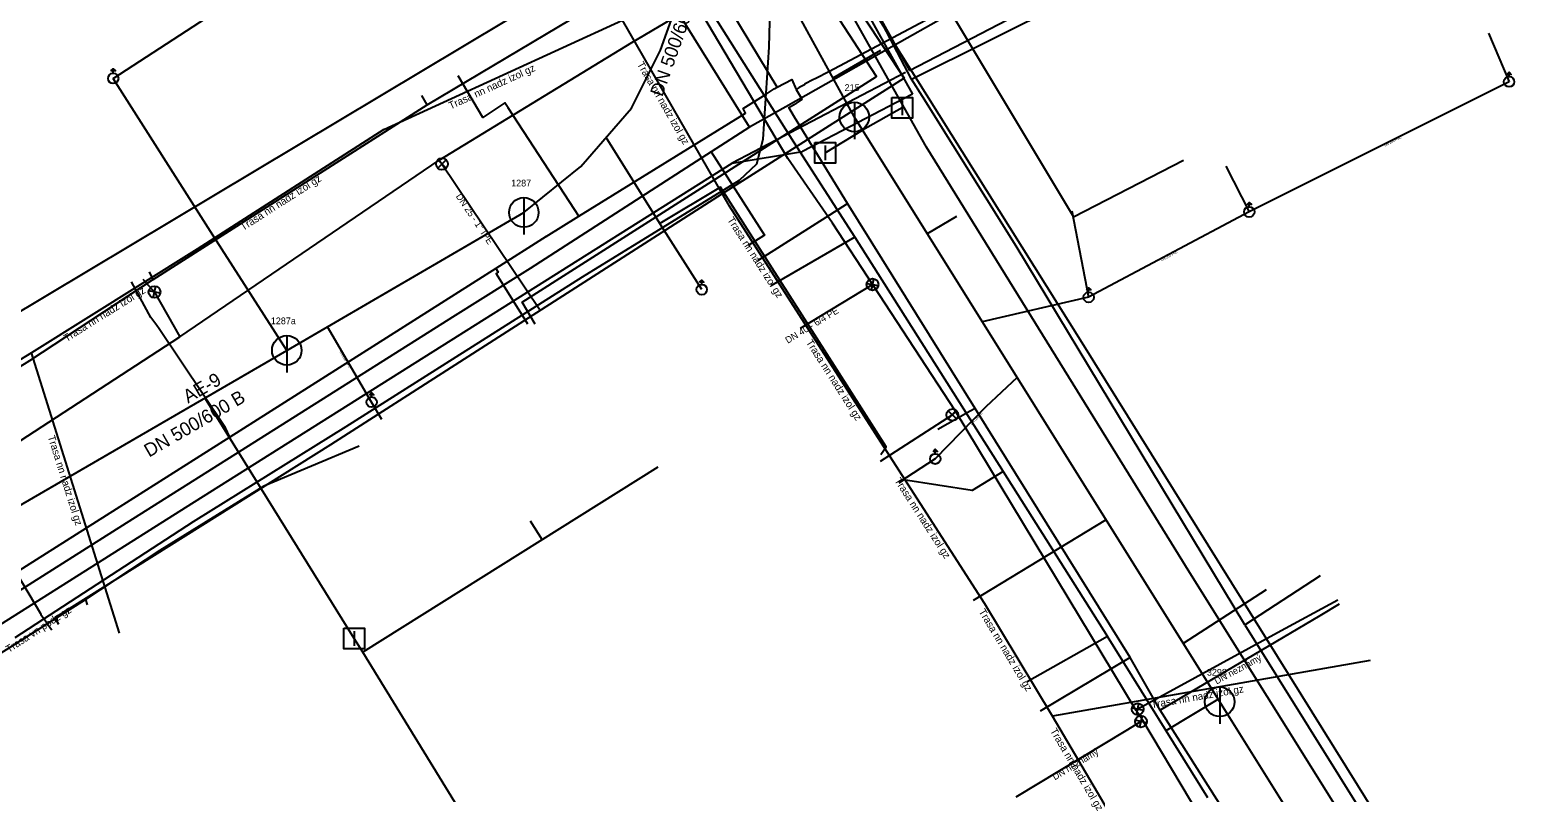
# Model space of a CAD drawing. Extents: x -493753 to -49291, y -1127285 to -112662.
# Drawn here: x -492897.5 to -492795.3, y -1126842.6 to -1126791 of the extents above; entities that cross this region are included whole.
import ezdxf

# ---------------------------------------------------------------- set-up
doc = ezdxf.new("R2010")
doc.units = 0
for name, color, linetype in [('Vrstva 1', 7, 'Continuous'), ('Vrstva 11', 7, 'Continuous'), ('Vrstva 15', 7, 'Continuous'), ('Vrstva 17', 7, 'Continuous'), ('Vrstva 19', 7, 'Continuous'), ('Vrstva 20', 7, 'Continuous'), ('Vrstva 22', 7, 'Continuous'), ('Vrstva 24', 7, 'Continuous'), ('Vrstva 26', 7, 'Continuous'), ('Vrstva 37', 7, 'Continuous'), ('Vrstva 39', 7, 'Continuous'), ('Vrstva 5', 7, 'Continuous'), ('Vrstva 6', 7, 'Continuous'), ('Vrstva 9', 7, 'Continuous')]:
    doc.layers.add(name, color=color, linetype=linetype)

# ---------------------------------------------------------------- blocks, each defined once
blk = doc.blocks.new('_UZAV0')
at = {"layer": 'Vrstva 1'}
for p, q in [((-0.035, -0.035), (0.035, 0.035)), ((0.035, -0.035), (-0.035, 0.035))]:
    blk.add_line(p, q, dxfattribs=at)
for radius in [0.05, 0.0025]:
    blk.add_circle((0, 0), radius, dxfattribs=at)
blk = doc.blocks.new('_VPUST')
at = {"layer": 'Vrstva 1'}
blk.add_line((0, 0.025), (0, -0.025), dxfattribs=at)
blk.add_lwpolyline([(-0.035, 0.035), (0.035, 0.035), (0.035, -0.035), (-0.035, -0.035), (-0.035, 0.035)], dxfattribs=at)
blk = doc.blocks.new('_SACHT')
at = {"layer": 'Vrstva 1'}
blk.add_line((0, 0.035), (0, 0.05), dxfattribs=at)
blk.add_lwpolyline([(-0.015, 0.05), (0, 0.065), (0.015, 0.05), (0.0025, 0.05)], close=True, dxfattribs=at)
blk.add_circle((0, 0), 0.035, dxfattribs=at)
blk = doc.blocks.new('_SACH0')
at = {"layer": 'Vrstva 1'}
blk.add_line((0, 0.05), (0, -0.075), dxfattribs=at)
blk.add_circle((0, 0), 0.05, dxfattribs=at)

msp = doc.modelspace()

# ---------------------------------------------------------------- linework, layer by layer
at = {"layer": 'Vrstva 1'}
for p, q in [((-492846.86, -1126794.83), (-492851.27, -1126787.5)), ((-492843.3, -1126803.48), (-492842.1, -1126802.71)), ((-492833.45, -1126816.59), (-492833.79, -1126816.78)), ((-492833.79, -1126816.78), (-492835.97, -1126818)), ((-492808.78, -1126829.85), (-492810.11, -1126830.63)), ((-492810.11, -1126830.63), (-492820.92, -1126837.03)), ((-492896.08, -1126831.47), (-492896, -1126831.58)), ((-492822.95, -1126833.45), (-492829.05, -1126837.09))]:
    msp.add_line(p, q, dxfattribs=at)
for points in [[(-492836.47, -1126790.12), (-492839.74, -1126791.86), (-492843.37, -1126793.78), (-492844.25, -1126794.24), (-492844.25, -1126794.24), (-492844.44, -1126794.34), (-492844.96, -1126794.61), (-492845.01, -1126794.66), (-492845.36, -1126794.86), (-492845.58, -1126794.99)], [(-492860.3, -1126803.57), (-492860.6, -1126803.11), (-492865.08, -1126796.23), (-492865.31, -1126795.89), (-492866.8, -1126796.88), (-492868.46, -1126794.05)], [(-492862.5, -1126804.93), (-492860.3, -1126803.57), (-492849.36, -1126796.81), (-492849.01, -1126796.59), (-492849.17, -1126796.27), (-492847.6, -1126795.29), (-492847.06, -1126794.95), (-492846.86, -1126794.83), (-492845.87, -1126794.31), (-492845.58, -1126794.99), (-492845.24, -1126795.55), (-492845.18, -1126795.67), (-492845.59, -1126795.94)], [(-492845.69, -1126796.86), (-492846.08, -1126796.21), (-492845.59, -1126795.94)], [(-492785.47, -1126893.44), (-492789.17, -1126887.53), (-492793.46, -1126880.64), (-492799.87, -1126870.52), (-492802.28, -1126866.71), (-492807.06, -1126859.45), (-492812.73, -1126850.83), (-492816.5, -1126843.99), (-492820.92, -1126837.03), (-492822.95, -1126833.45), (-492833.45, -1126816.59), (-492842.1, -1126802.71), (-492845.69, -1126796.86)], [(-492848.18, -1126806.57), (-492847.74, -1126806.29), (-492843.3, -1126803.48)], [(-492862.5, -1126804.93), (-492865.92, -1126807.1), (-492883.94, -1126818.54), (-492898.42, -1126827.7), (-492903.21, -1126830.75), (-492903.38, -1126830.86), (-492903.38, -1126830.86), (-492905.79, -1126832.39), (-492910.03, -1126835.06), (-492919.37, -1126840.86)], [(-492865.92, -1126807.1), (-492865.76, -1126807.36), (-492865.89, -1126807.44), (-492865.84, -1126807.52)], [(-492863.74, -1126810.87), (-492864.11, -1126810.28), (-492864.65, -1126809.43), (-492865.84, -1126807.52)], [(-492883.94, -1126818.54), (-492884.24, -1126817.89), (-492888.73, -1126811.2), (-492888.89, -1126810.97), (-492889.28, -1126810.42), (-492890.61, -1126808.01)], [(-492898.42, -1126827.7), (-492896.77, -1126830.47), (-492896.73, -1126830.54), (-492896.42, -1126830.98), (-492896.34, -1126831.1), (-492896.08, -1126831.47)]]:
    msp.add_lwpolyline(points, dxfattribs=at)
at = {"layer": 'Vrstva 11'}
for points in [[(-492848.73, -1126797.53), (-492854.56, -1126788.15), (-492854.38, -1126786.02), (-492853.2, -1126784.39), (-492859.9, -1126772.1), (-492871.87, -1126750.4), (-492886.74, -1126723.34), (-492898.4, -1126701.86), (-492908, -1126684.26), (-492916.54, -1126668.65), (-492921.45, -1126660.08), (-492926.55, -1126650.44), (-492932.03, -1126640.6), (-492935.8, -1126632.89)], [(-492799.37, -1126772.01), (-492815.12, -1126779.81), (-492834.32, -1126789.41), (-492840.18, -1126792.71), (-492846.28, -1126796.15), (-492848.73, -1126797.53)], [(-492841.39, -1126779.25), (-492846.47, -1126781.81), (-492838.25, -1126794.22), (-492850.91, -1126802.26), (-492877.11, -1126819.04), (-492895.8, -1126830.76), (-492895.54, -1126831.19)], [(-492841.39, -1126779.25), (-492828.07, -1126801.46)], [(-492848.73, -1126797.53), (-492851.33, -1126799.21)], [(-492851.33, -1126799.21), (-492863.6, -1126807.1), (-492868.67, -1126810.3), (-492890.52, -1126824.08), (-492904.79, -1126833.09), (-492915.31, -1126839.73), (-492925.93, -1126846.41)], [(-492851.33, -1126799.21), (-492847.71, -1126804.84), (-492848.82, -1126805.56)], [(-492828.07, -1126801.46), (-492826.79, -1126803.6), (-492819.34, -1126799.76)]]:
    msp.add_lwpolyline(points, dxfattribs=at)
at = {"layer": 'Vrstva 15'}
for p, q in [((-492891.84, -1126794.23), (-492875.54, -1126783.64)), ((-492841.63, -1126796.85), (-492848.75, -1126783.83)), ((-492798.67, -1126791.17), (-492797.28, -1126794.46)), ((-492839.87, -1126792.35), (-492843.08, -1126794.21)), ((-492797.28, -1126794.46), (-492814.88, -1126803.28)), ((-492838.39, -1126796.23), (-492841.08, -1126797.74)), ((-492816.88, -1126836.45), (-492841.63, -1126796.85)), ((-492854.81, -1126804.05), (-492858.44, -1126798.23)), ((-492843.61, -1126799.27), (-492841.08, -1126797.74)), ((-492816.47, -1126800.17), (-492814.88, -1126803.28)), ((-492880.08, -1126812.65), (-492864.02, -1126803.31)), ((-492826.9, -1126803.21), (-492825.76, -1126809.06)), ((-492814.88, -1126803.28), (-492825.76, -1126809.06)), ((-492834.72, -1126803.58), (-492836.69, -1126804.76)), ((-492825.76, -1126809.06), (-492832.97, -1126810.71)), ((-492874.33, -1126816.16), (-492877.33, -1126811.05)), ((-492906.42, -1126827.95), (-492880.08, -1126812.65)), ((-492875.51, -1126832.17), (-492885.63, -1126815.87)), ((-492873.65, -1126817.33), (-492874.33, -1126816.16)), ((-492854.94, -1126820.56), (-492874.93, -1126833.1)), ((-492836.15, -1126820), (-492838.63, -1126821.59)), ((-492863.59, -1126824.19), (-492862.78, -1126825.48)), ((-492833.55, -1126829.56), (-492824.59, -1126824.12)), ((-492813.74, -1126828.87), (-492819.35, -1126832.51)), ((-492874.93, -1126833.1), (-492875.51, -1126832.17)), ((-492866.83, -1126846.29), (-492874.93, -1126833.1)), ((-492820.5, -1126838.4), (-492816.99, -1126836.28)), ((-492782.29, -1126891.79), (-492816.88, -1126836.45))]:
    msp.add_line(p, q, dxfattribs=at)
for points in [[(-492864.02, -1126803.31), (-492860.16, -1126800.21), (-492856.72, -1126796.26), (-492854.76, -1126792.33), (-492853.47, -1126788.71), (-492852.82, -1126784.59), (-492852.84, -1126780.6), (-492853.67, -1126775.98), (-492855.18, -1126772.05)], [(-492880.08, -1126812.65), (-492885.25, -1126804.6), (-492891.84, -1126794.23)], [(-492839.83, -1126819.71), (-492839.48, -1126819.19), (-492850.69, -1126801.61), (-492854.81, -1126804.05)], [(-492851.97, -1126808.54), (-492854.69, -1126804.24), (-492854.81, -1126804.05)], [(-492830.61, -1126814.48), (-492832.73, -1126816.48), (-492836.15, -1126820)]]:
    msp.add_lwpolyline(points, dxfattribs=at)
at = {"layer": 'Vrstva 20'}
for p, q in [((-492845.27, -1126811.15), (-492840.4, -1126808.19)), ((-492808.87, -1126829.56), (-492812.97, -1126831.79)), ((-492830.67, -1126842.89), (-492823.22, -1126838.39))]:
    msp.add_line(p, q, dxfattribs=at)
for points in [[(-492970.22, -1126863.36), (-492958.22, -1126855.33), (-492945.51, -1126848.03), (-492940.77, -1126845.12), (-492925.74, -1126835.49), (-492904.65, -1126823), (-492904.05, -1126822.61), (-492887.33, -1126811.73), (-492869.75, -1126799.77), (-492856.71, -1126791.8), (-492853.07, -1126789.65)], [(-492786.68, -1126894.07), (-492787.42, -1126892.88), (-492788.56, -1126891.12), (-492791.28, -1126887.34), (-492800.45, -1126872.14), (-492806.36, -1126863.49), (-492810.7, -1126856.3), (-492813.24, -1126852.47), (-492818.85, -1126843.14), (-492822.1, -1126837.71), (-492822.55, -1126837.04), (-492834.77, -1126816.78), (-492843.12, -1126804.04), (-492846.14, -1126799.66), (-492852.32, -1126789.23)], [(-492869.75, -1126799.77), (-492869.57, -1126800.03), (-492862.95, -1126809.86)], [(-492889.83, -1126807.82), (-492889.04, -1126808.7), (-492887.33, -1126811.73)], [(-492834.77, -1126816.78), (-492834.99, -1126817.02), (-492839.88, -1126820.17)], [(-492812.97, -1126831.79), (-492822.44, -1126836.95), (-492822.55, -1126837.04)], [(-492823.22, -1126838.39), (-492822.22, -1126837.79), (-492822.1, -1126837.71)]]:
    msp.add_lwpolyline(points, dxfattribs=at)
at = {"layer": 'Vrstva 26'}
for p, q in [((-492861.22, -1126753.01), (-492837.7, -1126795.29)), ((-492860.7, -1126752.71), (-492837.9, -1126793.7)), ((-492837.9, -1126793.7), (-492813.31, -1126780.85)), ((-492836.75, -1126798.9), (-492842.69, -1126788.32)), ((-492838.16, -1126793.84), (-492849.91, -1126799.98)), ((-492837.7, -1126795.29), (-492845.15, -1126799.19)), ((-492849.91, -1126799.98), (-492845.15, -1126799.19)), ((-492824.87, -1126818.07), (-492836.75, -1126798.9)), ((-492886.94, -1126823.29), (-492849.91, -1126799.98)), ((-492818.91, -1126827.72), (-492824.87, -1126818.07)), ((-492921.27, -1126844.96), (-492886.94, -1126823.29)), ((-492808.42, -1126844.48), (-492818.91, -1126827.72))]:
    msp.add_line(p, q, dxfattribs=at)
at = {"layer": 'Vrstva 37'}
msp.add_line((-492859.57, -1126786.93), (-492899.16, -1126810.62), dxfattribs=at)
at = {"layer": 'Vrstva 39'}
for points in [[(-492837.75, -1126794.28), (-492844.99, -1126780.49)], [(-492870.58, -1126796.02), (-492853.69, -1126785.96)], [(-492853.69, -1126785.96), (-492845.76, -1126798.53), (-492841.59, -1126804.98)], [(-492837.75, -1126794.28), (-492821.94, -1126786.39)], [(-492837.02, -1126795.45), (-492837.75, -1126794.28)], [(-492889.14, -1126807.86), (-492870.58, -1126796.02)], [(-492870.58, -1126796.02), (-492870.94, -1126795.4)], [(-492815.19, -1126831.24), (-492830.68, -1126805.6), (-492837.02, -1126795.45)], [(-492841.59, -1126804.98), (-492847.28, -1126808.29)], [(-492841.59, -1126804.98), (-492831.56, -1126820.85)], [(-492889.14, -1126807.86), (-492889.39, -1126807.33)], [(-492889.14, -1126807.86), (-492897.51, -1126813.36), (-492916.14, -1126824.91), (-492935.64, -1126837.46), (-492943.74, -1126842.54)], [(-492875.17, -1126819.13), (-492881.63, -1126821.85), (-492888.69, -1126826.2), (-492893.71, -1126829.53)], [(-492831.56, -1126820.85), (-492833.65, -1126822.14), (-492838.3, -1126821.41), (-492838.63, -1126821.64)], [(-492831.56, -1126820.85), (-492824.48, -1126832.04)], [(-492815.19, -1126831.24), (-492810.05, -1126827.9)], [(-492913.49, -1126842), (-492910.42, -1126840.06), (-492907.08, -1126837.96), (-492893.71, -1126829.53)], [(-492893.71, -1126829.53), (-492893.61, -1126829.89)], [(-492824.48, -1126832.04), (-492829.93, -1126835.1)], [(-492817.68, -1126842.95), (-492824.48, -1126832.04)], [(-492815.19, -1126831.24), (-492804.46, -1126848.41)]]:
    msp.add_lwpolyline(points, dxfattribs=at)
at = {"layer": 'Vrstva 5'}
for points in [[(-492863.25, -1126810.88), (-492864.13, -1126809.38), (-492840.13, -1126794.11), (-492848.76, -1126780.82), (-492859.92, -1126760.67), (-492861.29, -1126757.87), (-492860.64, -1126755.54), (-492859.68, -1126754.76), (-492856.69, -1126753.45)], [(-492873.51, -1126797.69), (-492857.33, -1126790.3)], [(-492850.08, -1126802.88), (-492857.33, -1126790.3)], [(-492873.51, -1126797.69), (-492886.16, -1126805.8)], [(-492844.8, -1126811.12), (-492850.08, -1126802.88)], [(-492886.16, -1126805.8), (-492897.38, -1126812.82)], [(-492839.44, -1126819.49), (-492844.8, -1126811.12)], [(-492897.38, -1126812.82), (-492916.42, -1126824.45)], [(-492891.41, -1126831.8), (-492897.38, -1126812.82)], [(-492832.79, -1126829.81), (-492839.44, -1126819.49)], [(-492828.22, -1126837.42), (-492832.79, -1126829.81)], [(-492806.69, -1126833.65), (-492828.22, -1126837.42)], [(-492823.15, -1126846), (-492828.22, -1126837.42)]]:
    msp.add_lwpolyline(points, dxfattribs=at)
at = {"layer": 'Vrstva 6'}
for points in [[(-492898.47, -1126832.09), (-492886.41, -1126824.24), (-492876.05, -1126817.81), (-492860.04, -1126807.68), (-492849.41, -1126801.13), (-492848.23, -1126800.02), (-492847.8, -1126798.34), (-492847.4, -1126792.12), (-492847.23, -1126785.11), (-492846.68, -1126781.31), (-492846.74, -1126780.22), (-492852.23, -1126770.3), (-492858.08, -1126759.81), (-492859.14, -1126757.56), (-492858.99, -1126756.88), (-492856.69, -1126753.45)], [(-492856.69, -1126753.45), (-492858.36, -1126756.9), (-492854, -1126764.44), (-492846.25, -1126778.79), (-492844.82, -1126782.46), (-492836.75, -1126795.34), (-492826.22, -1126812.12), (-492807.54, -1126842.09), (-492794.08, -1126863.74), (-492778.12, -1126889.63)]]:
    msp.add_lwpolyline(points, dxfattribs=at)

# ---------------------------------------------------------------- block references
at = {"layer": 'Vrstva 17'}
for name, p, xscale, yscale in [('_SACHT', (-492891.84, -1126794.23), 9.998750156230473, 9.998750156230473), ('_SACHT', (-492797.28, -1126794.46), 9.998750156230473, 9.998750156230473), ('_SACH0', (-492841.63, -1126796.85), 19.997500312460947, 19.997500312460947), ('_VPUST', (-492838.39, -1126796.23), 19.997500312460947, 19.997500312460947), ('_VPUST', (-492843.61, -1126799.27), 19.997500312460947, 19.997500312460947), ('_SACH0', (-492864.02, -1126803.31), 19.997500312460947, 19.997500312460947), ('_SACHT', (-492814.88, -1126803.28), 9.998750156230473, 9.998750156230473), ('_SACHT', (-492851.97, -1126808.54), 9.998750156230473, 9.998750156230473), ('_SACHT', (-492825.76, -1126809.06), 9.998750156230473, 9.998750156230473), ('_SACH0', (-492880.08, -1126812.65), 19.997500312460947, 19.997500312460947), ('_SACHT', (-492874.33, -1126816.16), 9.998750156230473, 9.998750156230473), ('_SACHT', (-492836.15, -1126820), 9.998750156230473, 9.998750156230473), ('_VPUST', (-492875.51, -1126832.17), 19.997500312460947, 19.997500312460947), ('_SACH0', (-492816.88, -1126836.45), 19.997500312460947, 19.997500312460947)]:
    msp.add_blockref(name, p, dxfattribs=dict(at, xscale=xscale, yscale=yscale))
at = {"layer": 'Vrstva 22', "xscale": 7.999000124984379, "yscale": 7.999000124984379}
for p in [(-492869.57, -1126800.03), (-492834.99, -1126817.02)]:
    msp.add_blockref('_UZAV0', p, dxfattribs=at)
at = {"layer": 'Vrstva 22'}
for p, xscale, yscale, rotation in [((-492889.04, -1126808.7), 7.999000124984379, 7.99900012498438, 32.53708333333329), ((-492840.4, -1126808.19), 7.999000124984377, 7.999000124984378, -56.2388406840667), ((-492822.44, -1126836.95), 7.999000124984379, 7.999000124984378, -56.585208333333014), ((-492822.22, -1126837.79), 7.999000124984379, 7.999000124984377, 121.658366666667)]:
    msp.add_blockref('_UZAV0', p, dxfattribs=dict(at, xscale=xscale, yscale=yscale, rotation=rotation))

# ---------------------------------------------------------------- texts
at = {"layer": 'Vrstva 19'}
for s, height, rotation, p in [('DN 500/600 B', 0.9099, 70.4144, (-492854.64, -1126795.52)), ('DN 200 PVC', 0.16, 26.635, (-492805.69, -1126798.85)), ('DN 200 PVC', 0.16, 27.9687, (-492820.81, -1126806.62)), ('DN 200 PVC', 0.16, 300.3416, (-492876.51, -1126812.75)), ('AE-9', 0.91, 30.1603, (-492886.77, -1126816.26)), ('DN 500/600 B', 0.9099, 30.1603, (-492889.41, -1126819.92)), ('DN 250 PE', 0.16, 45.8129, (-492833.7, -1126817.71))]:
    msp.add_text(s, height=height, rotation=rotation, dxfattribs=at).set_placement(p)
for s, p in [('215', (-492842.29, -1126795.08)), ('1287', (-492864.88, -1126801.55)), ('1287a', (-492881.16, -1126810.88)), ('3298', (-492817.75, -1126834.68))]:
    msp.add_text(s, height=0.455, dxfattribs=at).set_placement(p)
at = {"layer": 'Vrstva 24'}
for s, rotation, p in [("DN 25 - 1'' IPE", 303.9582, (-492868.65, -1126802.22)), ('DN 40 - 6/4 PE', 31.3366, (-492846.14, -1126812.21)), ('DN neznámý', 28.5838, (-492817.09, -1126835.29)), ('DN neznámý', 31.0862, (-492828.05, -1126841.78))]:
    msp.add_text(s, height=0.455, rotation=rotation, dxfattribs=at).set_placement(p)
at = {"layer": 'Vrstva 9'}
for s, rotation, p in [('Trasa nn nadz izol gz', 299.9518, (-492856.37, -1126793.27)), ('Trasa nn nadz izol gz', 24.5439, (-492868.98, -1126796.34)), ('Trasa nn nadz izol gz', 32.6637, (-492883.03, -1126804.57)), ('Trasa nn nadz izol gz', 302.6487, (-492850.26, -1126803.81)), ('Trasa nn nadz izol gz', 32.0331, (-492894.99, -1126812.09)), ('Trasa nn nadz izol gz', 302.6317, (-492844.93, -1126812.11)), ('Trasa nn nadz izol gz', 287.4696, (-492896.28, -1126818.5)), ('Trasa nn nadz izol gz', 302.8241, (-492838.94, -1126821.47)), ('Trasa vn podz gz', 33.0606, (-492898.91, -1126833.15)), ('Trasa nn nadz izol gz', 300.9361, (-492833.23, -1126830.34)), ('Trasa nn nadz izol gz', 9.9413, (-492821.48, -1126836.9)), ('Trasa nn nadz izol gz', 300.5932, (-492828.39, -1126838.42))]:
    msp.add_text(s, height=0.5, rotation=rotation, dxfattribs=at).set_placement(p)

doc.saveas('drawing.dxf')
